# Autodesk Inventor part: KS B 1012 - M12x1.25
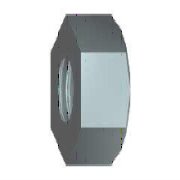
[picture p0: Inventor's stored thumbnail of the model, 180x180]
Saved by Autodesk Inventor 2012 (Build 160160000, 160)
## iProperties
IsCustomPart: 0
Created: 2009-02
Part Number: KS B 1012 - M12x1.25
Material: 강, 연강
Description: 6각 너트
Document SubType Name: Modeling
Standard: KS B 1012
Designer: KYOUNG IL JANG
Standards Organization: KS
Language: ko-KR
Size Designation: M12x1.25
Categories: <MemberInstance><Categories><Category DisplayName="조임쇠" InternalName="e4da775c-781d-43d5-af7c-5136215cf5a6" Mnemonic="FSTN"><Category DisplayName="너트" InternalN
Density: 1 g/cm^3
Author: KYOUNG IL JANG
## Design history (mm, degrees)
sketch "스케치1"
  geometry: L1 (10.97, 0)-(5.485, -9.5); L2 (5.485, -9.5)-(-5.485, -9.5); L3 (-5.485, -9.5)-(-10.97, 0); L4 (-10.97, 0)-(-5.485, 9.5); L5 (-5.485, 9.5)-(5.485, 9.5); L6 (5.485, 9.5)-(10.97, 0); 2 further points
  constraints: 12 end point, 1 coincident, 1 horizontal, 11 other
  dimensions: "d0" = 21.93931 distance of L1.start L3.end (= 1.1547 x SW)
extrude "본체" new body sketch "스케치1" distance "d1" = 10 (= KOH); taper "d2" = 0 deg
revolve "모따기3" stored, may be unused: angle "d5" = 90 deg
sketch "스케치2"
  geometry: 1 further point
hole "스레드" sketch "스케치2" diameter "d6" = 10.647; stored, may be unused: countersink angle "d10" = 82 deg, drill point angle "d12" = 118 deg; dims "d7" = 12.7, "d8" = 9.525, "d9" = 6.35, "d11" = 19.05
workaxis "Work Axis1"
workplane "Work Plane1"
body "Solid1"
chamfer "모따기1" distance "d13" = 0.67658 (= -0.5 x GD1 + 0.5 x NND); stored, may be unused: angle "d14" = 30 deg, second distance "d21" = 0.67658 (= -0.5 x GD1 + 0.5 x NND)
chamfer "모따기2" distance "d15" = 0.67658 (= -0.5 x GD1 + 0.5 x NND); stored, may be unused: angle "d16" = 30 deg, second distance "d22" = 0.67658 (= -0.5 x GD1 + 0.5 x NND)
sketch "스케치3"
  geometry: L1 (0, 10.97)-(10, 10.97) reference; L2 (10, 5.485)-(10, 10.97) reference; L3 (-2, 0)-(12, 0) reference; L4 (9.151, 10.97)-(10, 9.5)
  constraints: 2 end point, 2 point on line
  dimensions: "d3" = 19 diameter of L4.end L3 (= SW01); "d4" = 30 deg angle of L2 L4 (= ANG2)
other parameters: "ANG2" = 30 deg [user parameter; used in 1 equation term], "NND" = 12 [user parameter; used in 4 equation terms], "KOH" = 10 [user parameter; used in 1 equation term], "SW" = 19 [user parameter; used in 3 equation terms], "SW01" = 19 (= SW) [user parameter; used in 1 equation term], "GD1" = 10.64684 (computed from THREADDIA, PTC, TOA) [user parameter; used in 4 equation terms], "d19" = 0, "d20" = 0, "d24" = 0, "d25" = 0, "GUL" = 0.67658 (= 0.541266 x PTC) [user parameter], "TPU" = 8 (computed from PTC) [user parameter], "TOA" = 30 deg [user parameter; used in 1 equation term], "PTC" = 1.25 [user parameter; used in 4 equation terms], "E0" = 21.945 (= 1.155 x SW) [user parameter], "THREADDIA" = 12 [user parameter; used in 1 equation term], "GAL" = 0.67658 (= 0.541266 x PTC) [user parameter]
